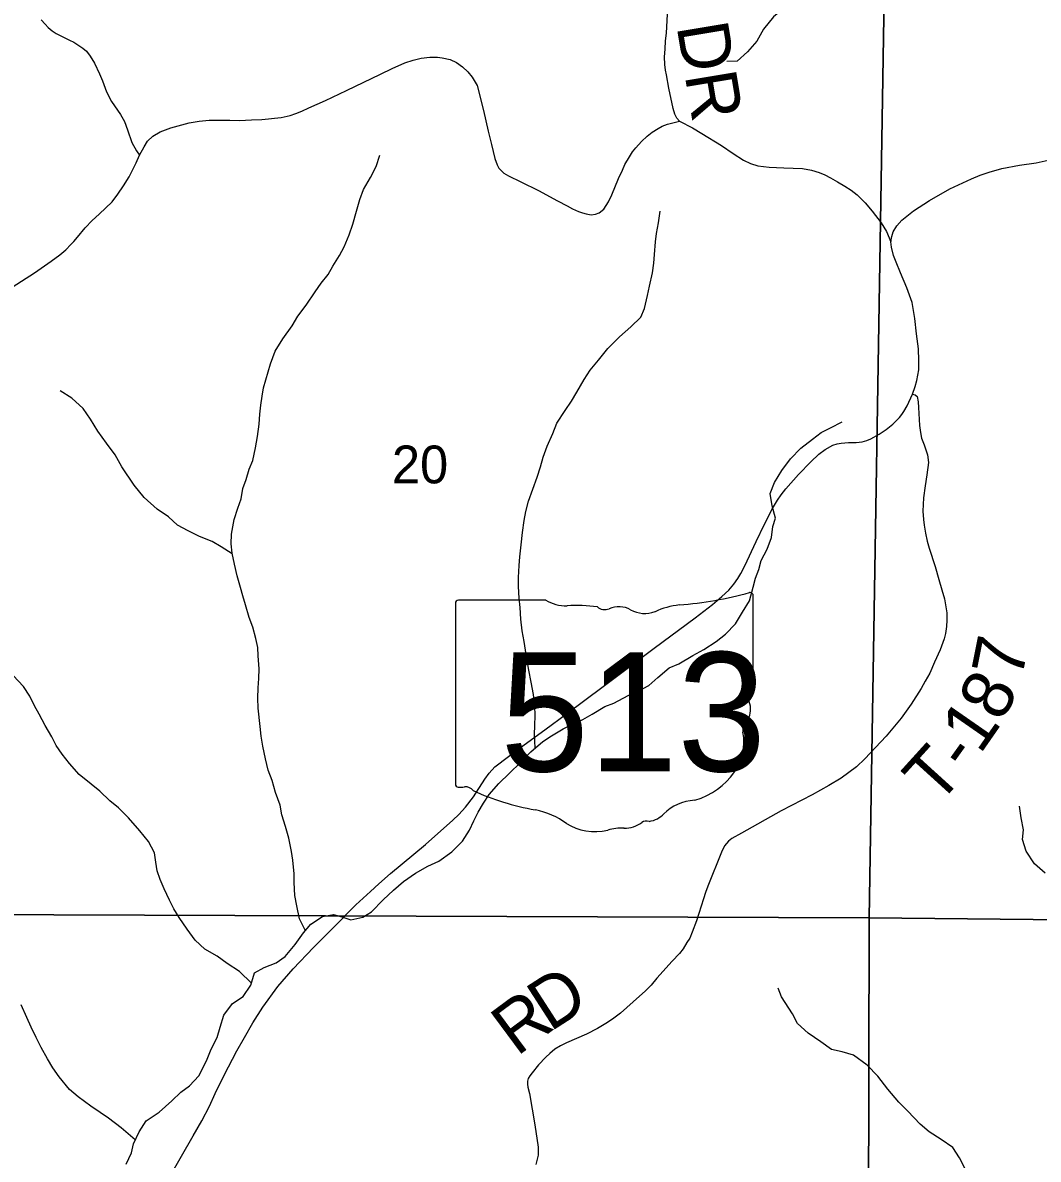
# Model space of a CAD drawing. Extents: x 0 to 191, y 0 to 55.
# Drawn here: x 186.378 to 187.502, y 49.124 to 50.382 of the extents above; entities that cross this region are included whole.
import ezdxf

# ---------------------------------------------------------------- set-up
doc = ezdxf.new("R2010")
doc.units = 0
for name, color, linetype in [('GM_X_Corporation', 7, 'Continuous'), ('GM_X_Minor_River', 7, 'Continuous'), ('GM_X_Section_Text', 7, 'Continuous'), ('GM_X_State_Location', 7, 'Continuous'), ('GM_X_State_Route', 7, 'Continuous'), ('GM_X_State_Shield', 7, 'Continuous'), ('GM_X_Township_Road', 7, 'Continuous'), ('GM_X_Township_Road_Text', 7, 'Continuous')]:
    doc.layers.add(name, color=color, linetype=linetype)

msp = doc.modelspace()

# ---------------------------------------------------------------- linework, layer by layer
at = {"layer": 'GM_X_Corporation'}
for points in [[(186.3245, 50.4222), (187.3319, 50.4112), (187.315, 49.3912), (186.3119, 49.3947)], [(187.3319, 50.4112), (188.3474, 50.3984), (188.3312, 49.3807), (187.315, 49.3912)], [(186.3119, 49.3947), (187.315, 49.3912), (187.3131, 48.3812), (187.3132, 48.3764), (186.3, 48.3895)], [(187.315, 49.3912), (188.3312, 49.3807), (188.327, 48.367), (187.3132, 48.3764), (187.3131, 48.3812)]]:
    msp.add_lwpolyline(points, close=True, dxfattribs=at)
at = {"layer": 'GM_X_Minor_River'}
for points in [[(187.3485, 50.5377), (187.3487, 50.5279), (187.3472, 50.5185), (187.345, 50.5063), (187.3427, 50.496), (187.3371, 50.4831), (187.3329, 50.4736), (187.3265, 50.4641), (187.3197, 50.4546), (187.3076, 50.4451), (187.2932, 50.4389), (187.2757, 50.4317), (187.2628, 50.424), (187.253, 50.4191), (187.2397, 50.413), (187.2253, 50.4011), (187.2094, 50.3882), (187.1981, 50.3745), (187.1909, 50.3615), (187.1803, 50.3497), (187.1689, 50.3391), (187.1575, 50.339)], [(186.6912, 49.3769), (186.6845, 49.39), (186.6815, 49.4044), (186.6795, 49.4158), (186.6788, 49.4302), (186.6787, 49.4397), (186.6772, 49.4549), (186.6756, 49.4644), (186.6726, 49.4792), (186.6691, 49.4921), (186.6649, 49.5053), (186.663, 49.5159), (186.658, 49.53), (186.6542, 49.5432), (186.65, 49.5546), (186.647, 49.5671), (186.6439, 49.5812), (186.6423, 49.5922), (186.6412, 49.6028), (186.6389, 49.6233), (186.6385, 49.6343), (186.6388, 49.6457), (186.6395, 49.6559), (186.6399, 49.6669), (186.6387, 49.681), (186.6383, 49.6905), (186.6364, 49.7003), (186.633, 49.7128), (186.6288, 49.7235), (186.6249, 49.7375), (186.6219, 49.7474), (186.6192, 49.7568), (186.6154, 49.7697), (186.6127, 49.7826), (186.61, 49.7948), (186.6089, 49.805), (186.6092, 49.8156), (186.6122, 49.832), (186.6164, 49.8445), (186.6201, 49.8548), (186.622, 49.8662), (186.6254, 49.8764), (186.6288, 49.8878), (186.6329, 49.8973), (186.6359, 49.9114), (186.6382, 49.9239), (186.6401, 49.9376), (186.6408, 49.9486), (186.6419, 49.9585), (186.6434, 49.9684), (186.6449, 49.9778), (186.6524, 50.0044), (186.6577, 50.0181), (186.666, 50.0318), (186.6763, 50.0463), (186.6827, 50.0569), (186.6918, 50.0691), (186.702, 50.0839), (186.7084, 50.0935), (186.7163, 50.103), (186.7216, 50.1125), (186.7288, 50.1243), (186.7341, 50.1338), (186.7394, 50.1471), (186.7435, 50.1589), (186.7477, 50.1733), (186.7515, 50.1862), (186.7556, 50.1973), (186.7632, 50.2106), (186.7696, 50.2227), (186.7734, 50.2353)], [(186.9456, 49.5793), (186.9448, 49.594), (186.9451, 49.6042), (186.9455, 49.6152), (186.9451, 49.6255), (186.9435, 49.6384), (186.9412, 49.652), (186.9385, 49.6653), (186.9366, 49.6759), (186.9347, 49.6873), (186.9332, 49.6968), (186.9312, 49.7089), (186.9297, 49.7218), (186.9289, 49.7347), (186.9277, 49.745), (186.927, 49.7579), (186.9269, 49.7678), (186.9277, 49.781), (186.9284, 49.7905), (186.9299, 49.8038), (186.9314, 49.8175), (186.9333, 49.8308), (186.9351, 49.841), (186.9381, 49.8521), (186.9427, 49.8654), (186.9476, 49.8787), (186.9513, 49.8901), (186.9543, 49.9011), (186.9589, 49.9132), (186.9649, 49.9273), (186.9694, 49.9387), (186.9785, 49.9528), (186.9857, 49.9631), (186.9914, 49.9729), (186.9997, 49.987), (187.0065, 49.9973), (187.0156, 50.0083), (187.0258, 50.0213), (187.0387, 50.0342), (187.0512, 50.0453), (187.0625, 50.0559), (187.0663, 50.0654), (187.0697, 50.0799), (187.0719, 50.0901), (187.0753, 50.1049), (187.0768, 50.1156), (187.0776, 50.1254), (187.0787, 50.1391), (187.0798, 50.1486), (187.082, 50.1604), (187.0839, 50.1733)], [(186.6102, 49.794), (186.5979, 49.8019), (186.588, 49.8076), (186.5739, 49.8132), (186.5614, 49.8193), (186.5496, 49.8257), (186.5397, 49.8348), (186.5272, 49.8434), (186.5127, 49.8563), (186.5017, 49.8699), (186.488, 49.8904), (186.4804, 49.9036), (186.4709, 49.9165), (186.4613, 49.9298), (186.4534, 49.943), (186.445, 49.9548), (186.4324, 49.9661), (186.4195, 49.9744)], [(187.1956, 49.7865), (187.2024, 49.799), (187.2069, 49.812), (187.2084, 49.8241), (187.2114, 49.8336), (187.2079, 49.8473), (187.2056, 49.8609), (187.2105, 49.8731), (187.2185, 49.8864), (187.2279, 49.899), (187.2397, 49.9108), (187.2526, 49.921), (187.262, 49.9283), (187.2723, 49.9336), (187.2852, 49.9401)], [(186.4927, 49.1187), (186.4988, 49.1312), (186.5007, 49.1411), (186.5071, 49.1544), (186.515, 49.1666), (186.5294, 49.1761), (186.5431, 49.1887), (186.5533, 49.1982), (186.5627, 49.2051), (186.5733, 49.2165), (186.5817, 49.2329), (186.5869, 49.2458), (186.5934, 49.2587), (186.5968, 49.2701), (186.6009, 49.2834), (186.6104, 49.2964), (186.6221, 49.304), (186.6308, 49.3165), (186.6346, 49.3302), (186.6456, 49.3363), (186.6588, 49.3413), (186.6687, 49.3482), (186.6797, 49.3615), (186.6891, 49.3744), (186.6971, 49.384), (186.7099, 49.3927), (186.7221, 49.3947), (186.7316, 49.3921), (186.7415, 49.3891), (186.7547, 49.3918), (186.7642, 49.3979), (186.7771, 49.4112), (186.7888, 49.4219), (186.7998, 49.4314), (186.8131, 49.4405), (186.8267, 49.4482), (186.8388, 49.4539), (186.8532, 49.4642), (186.865, 49.476), (186.8729, 49.4882), (186.8774, 49.4985), (186.8824, 49.508), (186.8884, 49.5182), (186.8945, 49.5277), (186.9051, 49.5399), (186.9172, 49.5514), (186.9293, 49.5632), (186.9406, 49.575), (186.9539, 49.5864), (186.9634, 49.5925), (186.9766, 49.6005), (186.9861, 49.6051), (186.9982, 49.6108), (187.0085, 49.6166), (187.0225, 49.625), (187.0324, 49.6288), (187.0483, 49.6372), (187.0578, 49.6414), (187.0714, 49.6483), (187.0812, 49.657), (187.0937, 49.6677), (187.1044, 49.6723), (187.1199, 49.6815), (187.132, 49.6883), (187.1457, 49.6971), (187.1563, 49.7051), (187.1673, 49.7165), (187.1748, 49.7295), (187.1828, 49.742), (187.1869, 49.7572), (187.1895, 49.7671), (187.1929, 49.7766), (187.1956, 49.7865)], [(186.6314, 49.3188), (186.6183, 49.3317), (186.6046, 49.3407), (186.5935, 49.3487), (186.5799, 49.3566), (186.5692, 49.3664), (186.5601, 49.3786), (186.5513, 49.3914), (186.5456, 49.4013), (186.5407, 49.4107), (186.5346, 49.4233), (186.5304, 49.4335), (186.5269, 49.4433), (186.5254, 49.4528), (186.5239, 49.4631), (186.5174, 49.4756), (186.5079, 49.4873), (186.4953, 49.5017), (186.4843, 49.513), (186.4748, 49.5206), (186.4637, 49.5312), (186.4539, 49.5391), (186.4406, 49.5497), (186.4299, 49.5618), (186.4219, 49.5724), (186.4154, 49.5819), (186.4105, 49.5914), (186.4032, 49.6039), (186.3964, 49.6164), (186.3914, 49.6258), (186.3861, 49.6364), (186.3789, 49.647), (186.3675, 49.6592)], [(187.5098, 49.4406), (187.498, 49.4508), (187.4888, 49.4648), (187.485, 49.4777), (187.4861, 49.4887), (187.4834, 49.502), (187.4815, 49.5149)], [(187.4217, 49.1127), (187.4152, 49.1256), (187.4076, 49.1369), (187.3947, 49.146), (187.3817, 49.1543), (187.3715, 49.163), (187.3578, 49.1774), (187.3479, 49.1872), (187.3357, 49.2016), (187.3247, 49.216), (187.3129, 49.2281), (187.2977, 49.2391), (187.2852, 49.2428), (187.2734, 49.2455), (187.2616, 49.2541), (187.2476, 49.2636), (187.2358, 49.2742), (187.2304, 49.2848), (187.2183, 49.3037), (187.2144, 49.3132)], [(186.5028, 49.1456), (186.4873, 49.1589), (186.4733, 49.1695), (186.4638, 49.1759), (186.4535, 49.1827), (186.4394, 49.1929), (186.4299, 49.2012), (186.4185, 49.2152), (186.4117, 49.2251), (186.4056, 49.2353), (186.3987, 49.2478), (186.393, 49.2588), (186.3877, 49.2701), (186.3827, 49.2808), (186.3766, 49.2948)]]:
    msp.add_lwpolyline(points, dxfattribs=at)
at = {"layer": 'GM_X_State_Route'}
msp.add_lwpolyline([(186.5409, 49.1051), (186.5669, 49.1501), (186.5765, 49.1665), (186.5848, 49.1827), (186.5911, 49.1966), (186.6012, 49.2171), (186.6151, 49.2439), (186.6237, 49.2589), (186.6328, 49.2748), (186.6441, 49.2923), (186.6605, 49.3151), (186.6775, 49.3348), (186.7001, 49.3583), (186.7219, 49.3801), (186.7471, 49.4057), (186.7631, 49.4204), (186.7723, 49.4287), (186.7854, 49.4401), (186.8239, 49.4725), (186.8542, 49.4992), (186.8608, 49.5055), (186.8683, 49.5136), (186.8771, 49.5252), (186.8896, 49.5446), (186.8945, 49.5511), (186.9008, 49.5583), (186.9158, 49.5696), (186.9332, 49.5826), (186.9562, 49.5994), (186.9801, 49.6169), (187.0206, 49.6472), (187.0772, 49.6895), (187.1224, 49.723), (187.1417, 49.738), (187.1522, 49.7469), (187.1597, 49.7538), (187.1653, 49.7604), (187.1698, 49.7668), (187.173, 49.7723), (187.1775, 49.7809), (187.1899, 49.8076), (187.1994, 49.827), (187.2081, 49.844), (187.2138, 49.8534), (187.2178, 49.8593), (187.223, 49.8661), (187.2368, 49.8818), (187.2506, 49.8959), (187.2596, 49.9042), (187.2666, 49.9095), (187.275, 49.9141), (187.2797, 49.9156), (187.284, 49.9165), (187.2921, 49.9171), (187.3008, 49.9172), (187.3073, 49.918), (187.3126, 49.9194), (187.317, 49.9213), (187.3264, 49.9265), (187.3338, 49.9315), (187.3413, 49.9375), (187.3487, 49.9449), (187.3514, 49.9482), (187.3537, 49.9514), (187.3572, 49.9576), (187.3631, 49.9707), (187.3662, 49.9792), (187.368, 49.9858), (187.3702, 49.9978), (187.3703, 50.0081), (187.3696, 50.0207), (187.3676, 50.0376), (187.3657, 50.0544), (187.3628, 50.0723), (187.357, 50.0885), (187.3497, 50.105), (187.3449, 50.1169), (187.342, 50.1241), (187.3398, 50.1332), (187.3392, 50.1392), (187.3401, 50.1453), (187.3417, 50.1502), (187.3458, 50.1571), (187.3513, 50.1634), (187.3642, 50.1734), (187.3819, 50.1852), (187.4046, 50.1981), (187.4283, 50.2091), (187.438, 50.2132), (187.448, 50.2164), (187.4619, 50.2204), (187.4816, 50.2241), (187.5, 50.2268), (187.5134, 50.2295)], dxfattribs=at)
at = {"layer": 'GM_X_State_Shield'}
for p, q in [((187.1869, 49.643), (187.1869, 49.7477)), ((186.8573, 49.7393), (186.8573, 49.5392)), ((186.9571, 49.7428), (186.8605, 49.7428)), ((187.1869, 49.6431), (187.1869, 49.643))]:
    msp.add_line(p, q, dxfattribs=at)
for centre, major_axis, start_param, end_param in [((187.0695, 50.0156), (0.3495, 0), 4.814394, 5.042369), ((187.1832, 49.7482), (0.00367, 0), 6.141152, 7.989035), ((186.8611, 49.7398), (0.00382, 0), 1.712693, 3.28349), ((186.9801, 49.766), (0.037, 0), 4.042523, 4.731795), ((186.9923, 49.6304), (0.133, 0), 1.404758, 1.657858), ((187.0225, 49.7408), (0.0107, 0), 3.836095, 5.185415), ((187.0382, 49.7177), (0.0222, 0), 0.950623, 2.079405), ((187.0669, 49.7494), (0.0267, 0), 4.081561, 5.145723), ((187.1141, 49.6816), (0.0703, 0), 1.699011, 2.107814), ((187.186, 49.6354), (0.00568, 0), 1.883978, 3.671073), ((187.1499, 49.6221), (0.0341, 0), 5.934695, 6.695948), ((187.183, 49.6426), (0.00393, 0), 5.05454, 6.418171), ((187.2, 49.5992), (0.0248, 0), 2.387724, 3.262537), ((187.0891, 49.5859), (0.0874, 0), 5.101752, 6.440018), ((186.8611, 49.5388), (0.00385, 0), 3.00124, 4.508301), ((186.8617, 49.5592), (0.0294, 0), 4.665946, 4.897461), ((186.8677, 49.5277), (0.0106, 0), 0.519207, 1.627899), ((187.0015, 49.7075), (0.2524, 0), 4.195997, 4.488961), ((187.1259, 49.483), (0.0479, 0), 1.647645, 2.488434), ((186.9263, 49.4493), (0.079, 0), 0.823519, 1.323587), ((187.0653, 49.5198), (0.0282, 0), 4.937069, 5.64225), ((187.0117, 49.5267), (0.0501, 0), 4.026481, 4.996735), ((187.0443, 49.5117), (0.0267, 0), 4.691044, 5.507374), ((187.0685, 49.4923), (0.00752, 0), 1.147584, 2.315152), ((187.0407, 49.4575), (0.0412, 0), 1.495662, 1.94098)]:
    msp.add_ellipse(centre, major_axis=major_axis, ratio=0.8, start_param=start_param, end_param=end_param, dxfattribs=at)
at = {"layer": 'GM_X_Township_Road'}
for points in [[(187.1052, 50.2728), (187.1023, 50.2763), (187.1002, 50.2806), (187.0981, 50.2869), (187.0935, 50.3095), (187.091, 50.324), (187.0899, 50.3293), (187.089, 50.3356), (187.0887, 50.3439), (187.0893, 50.3525), (187.0899, 50.3617), (187.0907, 50.3702), (187.092, 50.3911)], [(186.3988, 50.385), (186.4029, 50.3801), (186.4065, 50.3763), (186.4108, 50.3727), (186.4151, 50.3699), (186.4196, 50.3676), (186.4249, 50.3649), (186.4299, 50.3626), (186.4349, 50.3603), (186.4405, 50.3567), (186.4446, 50.3536), (186.4487, 50.3503), (186.4527, 50.3449), (186.4577, 50.3369), (186.4633, 50.3252), (186.4665, 50.3176), (186.4708, 50.3054), (186.4764, 50.2945), (186.4864, 50.2802), (186.4909, 50.2723), (186.4943, 50.2631), (186.499, 50.2493), (186.504, 50.2401), (186.5075, 50.2353)], [(186.3476, 50.0773), (186.3914, 50.1049), (186.4098, 50.1177), (186.4193, 50.125), (186.4258, 50.1304), (186.4315, 50.1362), (186.4348, 50.1398), (186.4387, 50.1445), (186.4472, 50.1547), (186.4551, 50.1629), (186.4627, 50.17), (186.4774, 50.1835), (186.4836, 50.192), (186.4899, 50.2013), (186.496, 50.2113), (186.5013, 50.2217), (186.5037, 50.2268), (186.5075, 50.2353), (186.5127, 50.2443), (186.5164, 50.2506), (186.5222, 50.2561), (186.5303, 50.2611), (186.5421, 50.2653), (186.5624, 50.271), (186.5737, 50.2727), (186.5846, 50.2739), (186.5971, 50.2741), (186.6074, 50.274), (186.6183, 50.2735), (186.6316, 50.2742), (186.643, 50.2748), (186.6504, 50.2755), (186.6569, 50.2761), (186.6644, 50.277), (186.6741, 50.2792), (186.6807, 50.2814), (186.687, 50.2839), (186.695, 50.2875), (186.7134, 50.2958), (186.7366, 50.3068), (186.7741, 50.3248), (186.787, 50.3312), (186.8011, 50.3373), (186.8105, 50.3405), (186.8192, 50.3424), (186.8289, 50.3437), (186.8372, 50.3436), (186.8424, 50.343), (186.8512, 50.3409), (186.8583, 50.3376), (186.865, 50.3331), (186.8708, 50.3274), (186.8758, 50.3215), (186.8811, 50.3124), (186.8881, 50.2846), (186.8936, 50.2618), (186.897, 50.2469), (186.9008, 50.2315), (186.9035, 50.2246), (186.9054, 50.2209), (186.9081, 50.2177), (186.9109, 50.2154), (186.9159, 50.2124), (186.9294, 50.2058), (186.9492, 50.1961), (186.9703, 50.1847), (186.9807, 50.1792), (186.9868, 50.1758), (186.9935, 50.1728), (186.998, 50.1712), (187.002, 50.1701), (187.0075, 50.1693), (187.0121, 50.17), (187.0163, 50.1714), (187.0213, 50.1753), (187.0265, 50.1836), (187.0303, 50.1914), (187.0377, 50.2092), (187.0421, 50.2187), (187.0448, 50.2248), (187.0498, 50.2332), (187.0533, 50.2387), (187.057, 50.2433), (187.063, 50.2504), (187.0694, 50.2563), (187.0751, 50.2607), (187.0815, 50.2648), (187.0861, 50.2673), (187.092, 50.2696), (187.1052, 50.2728)], [(187.1052, 50.2728), (187.1195, 50.2656), (187.1299, 50.2593), (187.1518, 50.2457), (187.1645, 50.2369), (187.1759, 50.2297), (187.1839, 50.2261), (187.1918, 50.2235), (187.2043, 50.2218), (187.2207, 50.2212), (187.2415, 50.2203), (187.2515, 50.2185), (187.2597, 50.216), (187.2661, 50.2136), (187.2724, 50.21), (187.28, 50.2058), (187.2883, 50.2009), (187.2952, 50.1966), (187.3018, 50.1912), (187.3107, 50.1825), (187.3185, 50.1733), (187.3286, 50.1603), (187.3343, 50.1508), (187.3392, 50.1392)], [(187.3631, 49.9707), (187.366, 49.9699), (187.3683, 49.968), (187.3694, 49.9621), (187.3698, 49.9558), (187.3707, 49.9361), (187.3718, 49.9284), (187.373, 49.9221), (187.376, 49.9145), (187.3797, 49.9035), (187.3807, 49.8952), (187.3791, 49.8813), (187.3771, 49.8693), (187.3754, 49.856), (187.3747, 49.8412), (187.3754, 49.8321), (187.376, 49.8258), (187.3776, 49.8167), (187.3793, 49.8081), (187.3815, 49.8002), (187.3881, 49.7798), (187.3924, 49.7655), (187.3956, 49.7542), (187.3987, 49.7441), (187.3998, 49.7374), (187.401, 49.7288), (187.4011, 49.7206), (187.4009, 49.7137), (187.3996, 49.706), (187.3982, 49.7), (187.3937, 49.6876), (187.3876, 49.674), (187.3823, 49.6621), (187.3773, 49.6529), (187.3726, 49.6451), (187.3616, 49.6276), (187.3504, 49.612), (187.3341, 49.5921), (187.3105, 49.5671), (187.3012, 49.5581), (187.284, 49.5458), (187.2705, 49.5376), (187.2521, 49.5272), (187.2176, 49.5097), (187.1737, 49.4849), (187.1631, 49.4789), (187.1596, 49.4761), (187.1549, 49.4708), (187.1516, 49.4639), (187.1365, 49.4262), (187.134, 49.4191), (187.1318, 49.4121), (187.1241, 49.3879), (187.1191, 49.3752), (187.1166, 49.3688), (187.1134, 49.3637), (187.1091, 49.357), (187.1051, 49.3516), (187.0972, 49.3434), (187.0801, 49.3245), (187.0737, 49.3167), (187.0671, 49.31), (187.0609, 49.3045), (187.0398, 49.2856), (187.0326, 49.2802), (187.0254, 49.2752), (187.0144, 49.2688), (187.0024, 49.2625), (186.9802, 49.2527), (186.9736, 49.2494), (186.9672, 49.2457), (186.9617, 49.2412), (186.9573, 49.237), (186.9492, 49.2284), (186.9421, 49.2198), (186.9395, 49.2162), (186.9378, 49.2132), (186.937, 49.2103), (186.9369, 49.2072), (186.9372, 49.2039), (186.939, 49.1968), (186.9449, 49.1622), (186.9488, 49.1373), (186.9486, 49.1284), (186.9462, 49.1182)]]:
    msp.add_lwpolyline(points, dxfattribs=at)

# ---------------------------------------------------------------- texts
at = {"layer": 'GM_X_Section_Text'}
msp.add_text('20', height=0.04186, rotation=0, dxfattribs=at).set_placement((186.7869, 49.872))
at = {"layer": 'GM_X_State_Location'}
for s in ['s', 'r']:
    msp.add_text(s, height=0.000189, dxfattribs=at).set_placement((187.0184, 49.626))
msp.add_text('513', height=0.000189, rotation=0, dxfattribs=at).set_placement((186.9515, 49.6122))
at = {"layer": 'GM_X_State_Shield'}
msp.add_text('513', height=0.13184, dxfattribs=at).set_placement((186.9068, 49.5533))
at = {"layer": 'GM_X_Township_Road_Text'}
for s, height, rotation, p in [('DR', 0.05682, 279.4626, (187.1019, 50.3781)), ('7', 0.0568, 78.6999, (187.4838, 49.6541)), ('8', 0.0568, 62.6028, (187.4619, 49.6066)), ('1', 0.0568, 55.2072, (187.4378, 49.5711)), ('T', 0.0568, 47.7799, (187.3907, 49.5143)), ('-', 0.0568, 54.3877, (187.4237, 49.5514)), ('D', 0.0568, 32.8302, (186.9618, 49.2643)), ('R', 0.0568, 36.5381, (186.9251, 49.2371))]:
    msp.add_text(s, height=height, rotation=rotation, dxfattribs=at).set_placement(p)

doc.saveas('drawing.dxf')
